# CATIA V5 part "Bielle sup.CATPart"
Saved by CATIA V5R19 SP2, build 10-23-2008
Part number: Bielle.1
Publications: "diamètre bielle", "Longueur bielle", "diamètre pivot", "epaisseur"
Bounding box of the stored display mesh (mm): x -5 to 5, y -10 to 210, z -10 to 10
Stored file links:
  C:\Users\pierre\Documents\IFMA\IAO\Bielle sup.CATPart
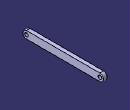
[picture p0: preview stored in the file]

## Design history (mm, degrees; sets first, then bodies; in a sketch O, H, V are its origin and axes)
Parameters
  `diamètre bielle` = 20 mm
  `Longueur bielle` = 200 mm
  `diamètre pivot` = 10 mm
  epaisseur = 5 mm
Body1 (main body)
  Point1: stored without definition
  Point2: stored without definition
  Sketch1 on yz-plane, origin (0, 0, 0), H (0, 1, 0), V (0, 0, 1)
    line L1 (200, 10) -> (0, 10)
    line L2 (0, -10) -> (200, -10)
    arc A1 centre (200, 0) radius 10 from (200, 10) to (200, -10) cw
    point P5 (200, 0)
    arc A2 centre (0, 0) radius 10 from (0, 10) to (0, -10) ccw
    point P6 (0, 0)
    reference projected point E1 (0, 0) from Point7
    reference projected point E2 (200, 0) from Point1
    distance L1 L2 = 20 {= `diamètre bielle`}
    tangency: A1 L2, A1 L1, A2 L1, L2 A2
    coincidence: P6 E1, P5 E2
  Pad1: profile Sketch1, direction (1, 0, 0), length 5, mirrored extent
  Point3: stored without definition
  Point4: stored without definition
  Sketch2 on yz-plane, origin (0, 0, 0), H (0, 1, 0), V (0, 0, 1)
    circle A1 centre (200, 0) radius 5
    point P1 (200, 0)
    circle A2 centre (0, 0) radius 5
    point P2 (0, 0)
    reference projected point E1 (0, 0) from Point4
    reference projected point E2 (200, 0) from Point1
    radius A1 = 5 {= `diamètre pivot` /2}
    radius A2 = 5 {= `diamètre pivot` /2}
    coincidence: E1 P2, E2 P1
  Pocket1: profile Sketch2, direction (-1, 0, 0), through (limit type 6), opposite side length 5
  Point5: (0, 0, 0)
  Point6: (0, 200, 0)
  Line1: type PtPt, FirstPoint Point5, SecondPoint Point6
  Plane1: type OffsetPt, RefPlane yz-plane, RefPoint Point5
  Point7: stored without definition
